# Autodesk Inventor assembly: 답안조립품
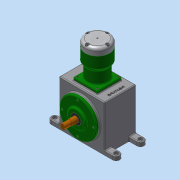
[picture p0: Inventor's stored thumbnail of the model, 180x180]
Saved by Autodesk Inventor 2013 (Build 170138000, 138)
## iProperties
Created: 2016-11
Part Number: 답안조립품
Document SubType Name: Assembly
Designer: Administrator
Author: Administrator
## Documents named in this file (16)
- C:\Users\Administrator\Desktop\361108V1014\답안조립품.iam
- C:\Users\Administrator\Desktop\361108V1014\본체.ipt
- C:\Users\Administrator\Desktop\361108V1014\베어링 20 x 47 x 14.ipt
- C:\Users\Administrator\Desktop\361108V1014\메인크랭크축.ipt
- C:\Users\Administrator\Desktop\361108V1014\베어링 NA 4902.ipt
- C:\Users\Administrator\Desktop\361108V1014\크랭크보조축.ipt
- C:\Users\Administrator\Desktop\361108V1014\앞커버.ipt
- C:\Users\Administrator\Desktop\361108V1014\오일 실 20 35 8.ipt
- C:\Users\Administrator\Desktop\361108V1014\실린더.ipt
- C:\Users\Administrator\Desktop\361108V1014\피스톤.ipt
- C:\Users\Administrator\Desktop\361108V1014\커넥팅로드.ipt
- C:\Users\Administrator\Desktop\361108V1014\피스톤핀.ipt
- C:\Users\Administrator\Desktop\361108V1014\실린더헤드.ipt
- C:\Users\Administrator\Desktop\361108V1014\가변스프링.ipt
- C:\Users\Administrator\Desktop\361108V1014\볼트 M4 x 8.ipt
- C:\Users\Administrator\Desktop\361108V1014\볼트 M5 x 20.ipt
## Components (15 placed, 5 different names)
1. 피스톤:1
2. 피스톤핀:1
3. 가변스프링:1
4. ISO 4762 M4 x 8:2
5. ISO 4762 M4 x 8:6
6. ISO 4762 M4 x 8:7
7. ISO 4762 M4 x 8:8
8. ISO 4762 M4 x 8:1
9. ISO 4762 M4 x 8:3
10. ISO 4762 M4 x 8:4
11. ISO 4762 M4 x 8:5
12. ISO 4762 M5 x 20:1
13. ISO 4762 M5 x 20:2
14. ISO 4762 M5 x 20:3
15. ISO 4762 M5 x 20:4
